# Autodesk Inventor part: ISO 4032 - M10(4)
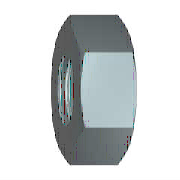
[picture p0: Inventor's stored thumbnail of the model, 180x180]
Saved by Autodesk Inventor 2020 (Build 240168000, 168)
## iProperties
Created: 2019-01
Part Number: ISO 4032 - M10(4)
Material: Nerezová ocel 440C
Description: Šestihranné matice, styl 1 – výrobní řada A a B
Document SubType Name: Modeling
Standard: ISO 4032
Designer: doma
Standard Revision: Fourth edition 2012-12-15
Standards Organization: ISO
Language: cs-CZ
Size Designation: M10
Categories: <MemberInstance><Categories><Category DisplayName="Spojovací materiál" InternalName="e4da775c-781d-43d5-af7c-5136215cf5a6" Mnemonic="FSTN"><Category DisplayName
Density: 7.75 g/cm^3
Appearance: Pololeštěná
IsCustomPart: 0
Author: doma
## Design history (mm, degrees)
sketch "Náčrt1"
  geometry: L1 (-9.238, 0)-(-4.619, 8); L2 (-4.619, 8)-(4.619, 8); L3 (4.619, 8)-(9.238, 0); L4 (9.238, 0)-(4.619, -8); L5 (4.619, -8)-(-4.619, -8); L6 (-4.619, -8)-(-9.238, 0); 2 further points
  constraints: 12 end point, 1 coincident, 1 horizontal, 11 other
  dimensions: "d0" = 18.47521 distance of L3.end L1.start (= 1.1547 x SW)
extrude "Těleso" new body sketch "Náčrt1" distance "d1" = 8.4 (= KOH); taper "d2" = 0 deg
sketch "Náčrt2"
  geometry: L1 (0, 4.619)-(0, 9.238) reference; L2 (0, 9.238)-(8.4, 9.238) reference; L3 (8.4, 4.619)-(8.4, 9.238) reference; L4 (-1.68, 0)-(10.08, 0) reference; L5 (1.119, 9.238)-(0, 7.3); L6 (7.281, 9.238)-(8.4, 7.3)
  constraints: 4 end point, 4 point on line
  dimensions: "d3" = 30 deg angle of L1 L5 (= ANG1); "d4" = 30 deg angle of L3 L6 (= ANG2); "d5" = 14.6 diameter of L5.end L4 (= SW0); "d6" = 14.6 diameter of L6.end L4 (= SW01)
revolve "Zkosení1" sketch "Náčrt2" stored, may be unused: angle "d7" = 90 deg
sketch "Náčrt3"
  geometry: 4 further points
  constraints: 1 coincident, 1 other
hole "Závit" sketch "Náčrt3" at (0, 0) diameter "d25" = 8.376; stored, may be unused: countersink angle "d29" = 82 deg, drill point angle "d31" = 118 deg; dims "d26" = 6, "d27" = 4, "d28" = 2, "d30" = 8
workaxis "Work Axis1"
workplane "Work Plane1"
body "Solid1"
chamfer "Zkosení2" distance "d8" = 0.8119 (= -0.5 x GD1 + 0.5 x NND); stored, may be unused: angle "d9" = 30 deg, second distance "d40" = 0.8119 (= -0.5 x GD1 + 0.5 x NND)
chamfer "Zkosení3" distance "d10" = 0.8119 (= -0.5 x GD1 + 0.5 x NND); stored, may be unused: angle "d11" = 30 deg, second distance "d41" = 0.8119 (= -0.5 x GD1 + 0.5 x NND)
other parameters: "ANG1" = 30 deg [user parameter; used in 1 equation term], "ANG2" = 30 deg [user parameter; used in 1 equation term], "KOH" = 8.4 [user parameter; used in 1 equation term], "SW" = 16 [user parameter; used in 2 equation terms], "SW0" = 14.6 [user parameter; used in 2 equation terms], "SW01" = 14.6 (= SW0) [user parameter; used in 1 equation term], "GD1" = 8.3762 (computed from THREADDIA, PTC, TOA) [user parameter; used in 4 equation terms], "d13" = 0, "d14" = 0, "d39" = 0, "d42" = 0, "GUL" = 0.8119 (= 0.541266 x PTC) [user parameter], "TPU" = 6.66667 (computed from PTC) [user parameter], "TOA" = 30 deg [user parameter; used in 1 equation term], "PTC" = 1.5 [user parameter; used in 4 equation terms], "E0" = 18.48 (= 1.155 x SW) [user parameter], "GAL" = 0.8119 (= 0.541266 x PTC) [user parameter]
